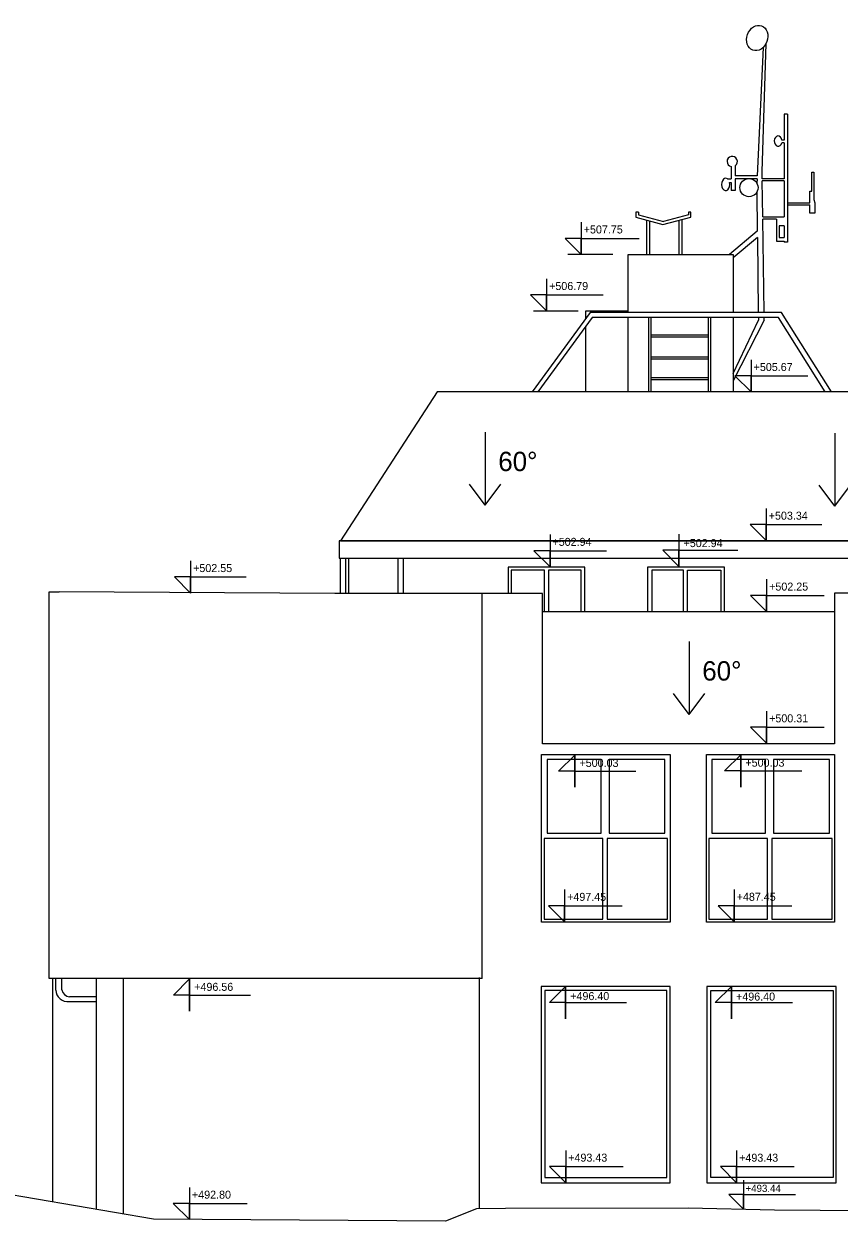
# Model space of a CAD drawing. Extents: x 3.3 to 94, y 492.8 to 514.5.
# Drawn here: x 17.19 to 29.8, y 492.81 to 511.36 of the extents above; entities that cross this region are included whole.
import ezdxf

# ---------------------------------------------------------------- set-up
doc = ezdxf.new("R2010")
doc.units = 0
for name, color, linetype in [('antena', 7, 'Continuous'), ('ocelova_konstrukce', 7, 'Continuous'), ('okap', 7, 'Continuous'), ('okna', 7, 'Continuous'), ('strecha_sikma', 7, 'Continuous'), ('teren', 7, 'Continuous'), ('zakl_tenka', 7, 'Continuous'), ('znaceni', 7, 'Continuous')]:
    doc.layers.add(name, color=color, linetype=linetype)

msp = doc.modelspace()

# ---------------------------------------------------------------- linework, layer by layer
at = {"layer": 'antena'}
for p, q in [((28.628, 510.996), (28.537, 509.008)), ((28.613, 509.071), (28.675, 511.058)), ((28.956, 509.96), (28.956, 509.56)), ((29.006, 509.96), (28.956, 509.96)), ((29.006, 509.96), (29.006, 507.98)), ((28.956, 509.52), (28.917, 509.52)), ((28.956, 509.56), (28.919, 509.56)), ((28.956, 509.52), (28.956, 508.962)), ((28.135, 509.15), (28.135, 508.962)), ((28.195, 509.163), (28.195, 509.008)), ((28.074, 508.962), (28.135, 508.962)), ((28.537, 509.008), (28.195, 509.008)), ((28.535, 508.962), (28.195, 508.962)), ((28.195, 508.962), (28.195, 508.779)), ((28.535, 508.962), (28.532, 508.891)), ((28.615, 508.962), (28.613, 509.071)), ((28.956, 508.962), (28.615, 508.962)), ((28.956, 508.931), (28.615, 508.931)), ((28.623, 508.371), (28.615, 508.931)), ((28.956, 508.931), (28.956, 508.371)), ((29.381, 508.767), (29.381, 509.062)), ((29.381, 509.062), (29.414, 509.062)), ((29.414, 509.062), (29.414, 508.642)), ((28.108, 508.906), (28.135, 508.906)), ((28.135, 508.906), (28.135, 508.779)), ((28.195, 508.779), (28.135, 508.779)), ((28.529, 508.752), (28.537, 508.149)), ((29.349, 508.767), (29.381, 508.767)), ((29.349, 508.587), (29.349, 508.767)), ((29.006, 508.587), (29.349, 508.587)), ((29.006, 508.556), (29.349, 508.556)), ((29.349, 508.427), (29.349, 508.556)), ((29.414, 508.642), (29.429, 508.587)), ((29.429, 508.587), (29.429, 508.427)), ((28.623, 508.371), (28.956, 508.371)), ((29.429, 508.427), (29.349, 508.427)), ((28.835, 508.336), (28.624, 508.336)), ((28.643, 506.89), (28.624, 508.336)), ((28.835, 508.336), (28.835, 507.996)), ((28.956, 508.231), (28.876, 508.231)), ((28.876, 508.231), (28.876, 508.051)), ((28.956, 508.231), (28.956, 508.051)), ((28.537, 508.149), (28.108, 507.787)), ((28.539, 508.049), (28.165, 507.736)), ((28.539, 508.049), (28.553, 506.89)), ((28.835, 507.996), (28.956, 507.996)), ((28.876, 508.051), (28.956, 508.051)), ((28.956, 507.996), (28.956, 507.98)), ((29.006, 507.98), (28.956, 507.98)), ((28.646, 506.772), (28.165, 505.83)), ((28.165, 505.942), (28.557, 506.772)), ((28.555, 506.813), (28.557, 506.772)), ((28.646, 506.772), (28.643, 506.813))]:
    msp.add_line(p, q, dxfattribs=at)
msp.add_circle((28.409, 508.824), 0.14, dxfattribs=at)
msp.add_arc((28.149, 509.229), 0.08, 304.739, 259.6209, dxfattribs=at)
msp.add_ellipse((28.537, 511.142), major_axis=(0.068, 0.188), ratio=0.8, dxfattribs=at)
for centre, major_axis, ratio, start_param, end_param in [((28.86, 509.545), (0, 0.08), 0.75, 4.901005, 10.677751), ((28.048, 508.875), (0, 0.096), 0.653945, 5.856319, 11.320091)]:
    msp.add_ellipse(centre, major_axis=major_axis, ratio=ratio, start_param=start_param, end_param=end_param, dxfattribs=at)
at = {"layer": 'ocelova_konstrukce'}
for p, q in [((26.7, 508.444), (26.66, 508.444)), ((26.66, 508.444), (26.66, 508.364)), ((26.7, 508.444), (26.7, 508.404)), ((26.7, 508.404), (27.088, 508.3)), ((27.075, 508.253), (27.511, 508.369)), ((27.475, 508.403), (27.088, 508.299)), ((27.475, 508.443), (27.475, 508.403)), ((27.511, 508.443), (27.475, 508.443)), ((27.511, 508.369), (27.511, 508.443)), ((26.66, 508.364), (27.075, 508.253)), ((26.823, 508.32), (26.823, 507.787)), ((26.868, 508.308), (26.868, 507.787)), ((27.325, 508.32), (27.325, 507.787)), ((27.369, 508.331), (27.369, 507.787)), ((25.948, 506.89), (25.053, 505.658)), ((28.915, 506.89), (25.948, 506.89)), ((29.685, 505.658), (28.915, 506.89)), ((25.981, 506.814), (25.142, 505.658)), ((28.868, 506.814), (25.981, 506.814)), ((26.854, 506.814), (26.854, 505.658)), ((26.894, 505.658), (26.894, 506.814)), ((27.776, 506.814), (27.776, 505.658)), ((27.816, 505.658), (27.816, 506.814)), ((29.59, 505.658), (28.868, 506.814)), ((26.894, 506.545), (27.776, 506.545)), ((27.776, 506.508), (26.894, 506.508)), ((26.894, 506.204), (27.776, 506.204)), ((27.776, 506.167), (26.894, 506.167)), ((26.894, 505.883), (27.776, 505.883)), ((27.776, 505.846), (26.894, 505.846))]:
    msp.add_line(p, q, dxfattribs=at)
at = {"layer": 'okap'}
for p, q in [((17.679, 496.391), (17.678, 496.569)), ((17.773, 496.395), (17.773, 496.569)), ((17.886, 496.214), (18.301, 496.214)), ((17.892, 496.29), (18.301, 496.29))]:
    msp.add_line(p, q, dxfattribs=at)
for points in [[(25.326, 503.354), (22.066, 503.354), (22.066, 503.081), (32.859, 503.081), (32.859, 503.354), (28.259, 503.354)], [(28.259, 503.354), (25.326, 503.354)], [(22.079, 503.081), (22.079, 502.536)], [(22.166, 502.536), (22.166, 503.081)], [(22.974, 503.081), (22.974, 502.536)], [(23.061, 502.536), (23.061, 503.081)]]:
    msp.add_lwpolyline(points, dxfattribs=at)
for centre, radius, start, end in [((17.864, 496.399), 0.186, 182.3773, 276.6353), ((17.901, 496.42), 0.131, 191.2731, 265.8341)]:
    msp.add_arc(centre, radius, start, end, dxfattribs=at)
at = {"layer": 'okna'}
for points in [[(25.242, 502.255), (25.242, 502.898), (24.726, 502.898), (24.726, 502.536)], [(25.812, 502.255), (25.812, 502.898), (25.305, 502.898), (25.305, 502.255)], [(27.396, 502.255), (27.396, 502.898), (26.903, 502.898), (26.903, 502.255)], [(27.459, 502.255), (27.459, 502.898), (27.972, 502.898), (27.972, 502.255)]]:
    msp.add_lwpolyline(points, dxfattribs=at)
for points in [[(26.119, 499.965), (25.284, 499.965), (25.284, 498.823), (26.119, 498.823)], [(27.108, 499.965), (26.243, 499.965), (26.243, 498.823), (27.108, 498.823)], [(28.667, 499.965), (27.832, 499.965), (27.832, 498.823), (28.667, 498.823)], [(29.656, 499.965), (28.791, 499.965), (28.791, 498.823), (29.656, 498.823)], [(26.147, 498.74), (25.238, 498.74), (25.238, 497.49), (26.147, 497.49)], [(26.215, 497.49), (27.149, 497.49), (27.149, 498.74), (26.215, 498.74)], [(28.695, 498.74), (27.786, 498.74), (27.786, 497.49), (28.695, 497.49)], [(28.763, 497.49), (29.697, 497.49), (29.697, 498.74), (28.763, 498.74)], [(27.138, 496.383), (25.249, 496.383), (25.249, 493.49), (27.138, 493.49)], [(27.817, 496.383), (29.712, 496.383), (29.712, 493.49), (27.817, 493.49)]]:
    msp.add_lwpolyline(points, close=True, dxfattribs=at)
at = {"layer": 'strecha_sikma'}
for p, q in [((23.58, 505.658), (22.085, 503.354)), ((31.313, 505.658), (23.58, 505.658)), ((22.085, 503.354), (25.353, 503.354)), ((25.326, 503.354), (28.259, 503.354)), ((28.259, 503.354), (32.859, 503.354)), ((25.211, 502.255), (29.735, 502.255)), ((29.735, 500.208), (25.211, 500.208))]:
    msp.add_line(p, q, dxfattribs=at)
at = {"layer": 'teren'}
for p, q in [((19.189, 492.845), (16.377, 493.324)), ((24.193, 493.005), (23.709, 492.813)), ((24.642, 493.008), (24.193, 493.005)), ((27.47, 493.011), (24.642, 493.008)), ((28.806, 492.984), (27.47, 493.011)), ((30.314, 492.969), (28.806, 492.984)), ((23.709, 492.813), (19.189, 492.845))]:
    msp.add_line(p, q, dxfattribs=at)
at = {"layer": 'zakl_tenka'}
for p, q in [((26.541, 507.787), (28.165, 507.787)), ((26.541, 506.89), (26.541, 507.787)), ((28.165, 507.787), (28.165, 506.89)), ((25.884, 506.803), (25.884, 506.914)), ((25.884, 506.914), (26.541, 506.914)), ((26.541, 505.658), (26.541, 506.814)), ((28.165, 506.814), (28.165, 505.658)), ((25.884, 505.658), (25.884, 506.68)), ((22.209, 503.081), (22.209, 502.536)), ((17.578, 496.569), (17.578, 502.561)), ((17.578, 502.561), (17.73, 502.56)), ((21.997, 502.536), (17.73, 502.56)), ((25.211, 502.536), (21.997, 502.536)), ((24.281, 496.569), (24.281, 502.536)), ((25.211, 500.208), (25.211, 502.536)), ((30.75, 502.542), (29.735, 502.542)), ((29.735, 502.542), (29.735, 500.208)), ((17.627, 496.569), (17.578, 496.569)), ((17.717, 496.569), (17.627, 496.569)), ((17.627, 496.569), (17.627, 493.111)), ((24.281, 496.569), (17.717, 496.569)), ((18.301, 496.569), (18.301, 492.996)), ((18.72, 496.569), (18.72, 492.924)), ((24.231, 496.586), (24.231, 493.005))]:
    msp.add_line(p, q, dxfattribs=at)
for points in [[(25.87, 502.255), (25.87, 502.943), (24.681, 502.943), (24.681, 502.536)], [(26.843, 502.255), (26.843, 502.948), (28.023, 502.948), (28.023, 502.255)]]:
    msp.add_lwpolyline(points, dxfattribs=at)
for points in [[(25.197, 500.042), (27.189, 500.042), (27.189, 497.444), (25.197, 497.444)], [(27.752, 500.042), (29.732, 500.042), (29.732, 497.444), (27.752, 497.444)], [(27.187, 496.448), (25.191, 496.448), (25.191, 493.407), (27.187, 493.407)], [(29.758, 496.448), (27.756, 496.448), (27.756, 493.407), (29.758, 493.407)]]:
    msp.add_lwpolyline(points, close=True, dxfattribs=at)
at = {"layer": 'znaceni'}
for p, q in [((25.812, 508.288), (25.812, 507.788)), ((25.812, 508.038), (25.562, 508.038)), ((25.562, 508.038), (25.812, 507.788)), ((25.812, 507.788), (25.812, 508.038)), ((25.812, 508.038), (26.707, 508.038)), ((26.3, 507.787), (25.607, 507.787)), ((25.276, 507.413), (25.276, 506.913)), ((25.276, 507.163), (25.026, 507.163)), ((25.026, 507.163), (25.276, 506.913)), ((25.276, 506.913), (25.276, 507.163)), ((25.276, 507.163), (26.152, 507.163)), ((25.765, 506.912), (25.071, 506.912)), ((28.442, 506.158), (28.442, 505.658)), ((28.442, 505.908), (28.192, 505.908)), ((28.192, 505.908), (28.442, 505.658)), ((28.442, 505.658), (28.442, 505.908)), ((28.442, 505.908), (29.318, 505.908)), ((24.325, 505.035), (24.325, 503.905)), ((29.739, 505.019), (29.739, 503.889)), ((24.325, 503.905), (24.084, 504.232)), ((24.325, 503.905), (24.566, 504.232)), ((29.739, 503.889), (29.498, 504.216)), ((29.739, 503.889), (29.979, 504.216)), ((28.676, 503.855), (28.676, 503.355)), ((28.676, 503.605), (28.426, 503.605)), ((28.426, 503.605), (28.676, 503.355)), ((28.676, 503.355), (28.676, 503.605)), ((28.676, 503.605), (29.535, 503.605)), ((25.329, 503.448), (25.329, 502.948)), ((27.323, 503.455), (27.323, 502.955)), ((25.329, 503.198), (25.079, 503.198)), ((25.079, 503.198), (25.329, 502.948)), ((25.329, 502.948), (25.329, 503.198)), ((25.329, 503.198), (26.203, 503.198)), ((27.323, 503.205), (27.073, 503.205)), ((27.073, 503.205), (27.323, 502.955)), ((27.323, 502.955), (27.323, 503.205)), ((27.323, 503.205), (28.238, 503.205)), ((19.765, 503.043), (19.765, 502.543)), ((19.765, 502.793), (19.515, 502.793)), ((19.515, 502.793), (19.765, 502.543)), ((19.765, 502.543), (19.765, 502.793)), ((19.765, 502.793), (20.626, 502.793)), ((28.682, 502.756), (28.682, 502.256)), ((28.682, 502.506), (28.432, 502.506)), ((28.432, 502.506), (28.682, 502.256)), ((28.682, 502.256), (28.682, 502.506)), ((28.682, 502.506), (29.572, 502.506)), ((27.483, 501.79), (27.483, 500.66)), ((27.483, 500.66), (27.242, 500.987)), ((27.483, 500.66), (27.724, 500.987)), ((28.682, 500.715), (28.682, 500.215)), ((28.682, 500.465), (28.432, 500.465)), ((28.432, 500.465), (28.682, 500.215)), ((28.682, 500.215), (28.682, 500.465)), ((28.682, 500.465), (29.572, 500.465)), ((25.462, 499.783), (25.712, 500.033)), ((25.712, 500.033), (25.712, 499.533)), ((25.712, 499.533), (25.712, 500.033)), ((25.712, 500.033), (25.712, 499.783)), ((28.031, 499.787), (28.281, 500.037)), ((28.281, 500.037), (28.281, 499.537)), ((28.281, 499.537), (28.281, 500.037)), ((28.281, 500.037), (28.281, 499.787)), ((25.712, 499.783), (25.462, 499.783)), ((25.712, 499.783), (25.462, 499.783)), ((25.712, 499.533), (25.712, 499.783)), ((25.712, 499.783), (26.658, 499.783)), ((25.712, 499.783), (26.658, 499.783)), ((28.281, 499.787), (28.031, 499.787)), ((28.281, 499.787), (28.031, 499.787)), ((28.281, 499.537), (28.281, 499.787)), ((28.281, 499.787), (29.226, 499.787)), ((28.281, 499.787), (29.226, 499.787)), ((25.555, 497.948), (25.555, 497.448)), ((28.181, 497.949), (28.181, 497.449)), ((25.555, 497.698), (25.305, 497.698)), ((25.305, 497.698), (25.555, 497.448)), ((25.555, 497.448), (25.555, 497.698)), ((25.555, 497.698), (26.445, 497.698)), ((28.181, 497.699), (27.931, 497.699)), ((27.931, 497.699), (28.181, 497.449)), ((28.181, 497.449), (28.181, 497.699)), ((28.181, 497.699), (29.07, 497.699)), ((19.498, 496.314), (19.748, 496.564)), ((19.748, 496.564), (19.748, 496.064)), ((19.748, 496.064), (19.748, 496.564)), ((19.748, 496.564), (19.748, 496.314)), ((19.748, 496.314), (19.498, 496.314)), ((19.748, 496.314), (19.498, 496.314)), ((19.748, 496.064), (19.748, 496.314)), ((19.748, 496.314), (20.693, 496.314)), ((19.748, 496.314), (20.693, 496.314)), ((25.319, 496.198), (25.569, 496.448)), ((25.569, 496.448), (25.569, 495.948)), ((25.569, 495.948), (25.569, 496.448)), ((25.569, 496.448), (25.569, 496.198)), ((27.886, 496.198), (28.136, 496.448)), ((28.136, 496.448), (28.136, 495.948)), ((28.136, 495.948), (28.136, 496.448)), ((28.136, 496.448), (28.136, 496.198)), ((25.569, 496.198), (25.319, 496.198)), ((25.569, 496.198), (25.319, 496.198)), ((25.569, 495.948), (25.569, 496.198)), ((25.569, 496.198), (26.515, 496.198)), ((25.569, 496.198), (26.515, 496.198)), ((28.136, 496.198), (27.886, 496.198)), ((28.136, 496.198), (27.886, 496.198)), ((28.136, 495.948), (28.136, 496.198)), ((28.136, 496.198), (29.081, 496.198)), ((28.136, 496.198), (29.081, 496.198)), ((25.572, 493.908), (25.572, 493.408)), ((28.218, 493.908), (28.218, 493.408)), ((25.572, 493.658), (25.322, 493.658)), ((25.322, 493.658), (25.572, 493.408)), ((25.572, 493.408), (25.572, 493.658)), ((25.572, 493.658), (26.462, 493.658)), ((28.218, 493.658), (27.968, 493.658)), ((27.968, 493.658), (28.218, 493.408)), ((28.218, 493.408), (28.218, 493.658)), ((28.218, 493.658), (29.108, 493.658)), ((28.324, 493.448), (28.324, 492.997)), ((19.747, 493.335), (19.747, 492.835)), ((28.324, 493.223), (28.098, 493.223)), ((28.098, 493.223), (28.324, 492.997)), ((28.324, 492.997), (28.324, 493.223)), ((28.324, 493.223), (29.128, 493.223)), ((19.747, 493.085), (19.497, 493.085)), ((19.497, 493.085), (19.747, 492.835)), ((19.747, 492.835), (19.747, 493.085)), ((19.747, 493.085), (20.642, 493.085))]:
    msp.add_line(p, q, dxfattribs=at)

# ---------------------------------------------------------------- texts
for s, height, p in [('+507.75', 0.124, (25.851, 508.114)), ('+506.79', 0.124, (25.315, 507.238)), ('+505.67', 0.124, (28.481, 505.983)), ('60°', 0.3, (24.528, 504.432)), ('+503.34', 0.124, (28.715, 503.68)), ('+502.94', 0.124, (25.367, 503.274)), ('+502.94', 0.124, (27.396, 503.255)), ('+502.55', 0.124, (19.804, 502.868)), ('+502.25', 0.124, (28.721, 502.581)), ('60°', 0.3, (27.686, 501.187)), ('+500.31', 0.124, (28.721, 500.54)), ('+500.03', 0.124, (25.785, 499.849)), ('+500.03', 0.124, (28.354, 499.853)), ('+497.45', 0.124, (25.594, 497.774)), ('+487.45', 0.124, (28.219, 497.775)), ('+496.56', 0.124, (19.821, 496.38)), ('+496.40', 0.124, (25.642, 496.237)), ('+496.40', 0.124, (28.209, 496.229)), ('+493.43', 0.124, (25.611, 493.734)), ('+493.43', 0.124, (28.257, 493.733)), ('+493.44', 0.112, (28.356, 493.264)), ('+492.80', 0.124, (19.786, 493.16))]:
    msp.add_text(s, height=height, dxfattribs=at).set_placement(p)

doc.saveas('drawing.dxf')
